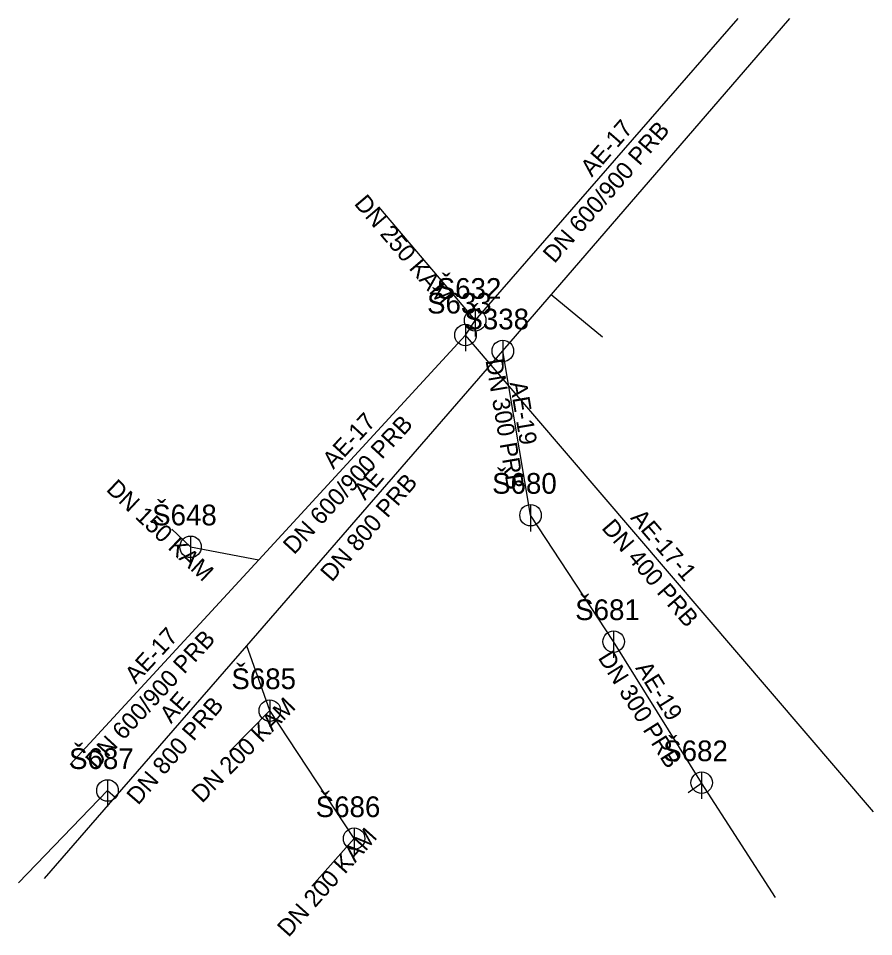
# Model space of a CAD drawing. Extents: x -483422.7 to -483343.1, y -1126332.9 to -1126247.5.
import ezdxf

# ---------------------------------------------------------------- set-up
doc = ezdxf.new("R2010")
doc.units = 0
for name, color, linetype in [('_pripojka_kanal_destova_priblizne_', 7, 'Continuous'), ('_pripojka_kanal_jednotna_priblizne_', 7, 'Continuous'), ('_stoka_jednotna_smvak_prevzato_z_dokumentace_', 7, 'Continuous'), ('Default', 7, 'Continuous'), ('MoLevel 119', 7, 'Continuous'), ('MoLevel 120', 7, 'Continuous'), ('MoLevel 124', 7, 'Continuous'), ('MoLevel 68', 7, 'Continuous'), ('MoLevel 69', 7, 'Continuous')]:
    doc.layers.add(name, color=color, linetype=linetype)

# ---------------------------------------------------------------- blocks, each defined once
blk = doc.blocks.new('_sachta_kanal_prevzato_z_dokumentace_')
at = {"layer": 'Default'}
blk.add_line((0, 0.00005), (0, -0.000075), dxfattribs=at)
blk.add_circle((0, 0), 0.00005, dxfattribs=at)

msp = doc.modelspace()

# ---------------------------------------------------------------- linework, layer by layer
at = {"layer": '_pripojka_kanal_destova_priblizne_'}
msp.add_line((-483368.347, -1126277.171), (-483373.113, -1126273.232), dxfattribs=at)
at = {"layer": '_pripojka_kanal_jednotna_priblizne_'}
for p, q in [((-483389.194, -1126265.038), (-483380.194, -1126275.606)), ((-483408.416, -1126295.029), (-483406.669, -1126296.67)), ((-483403.061, -1126315.703), (-483399.299, -1126311.9)), ((-483360.379, -1126319.511), (-483359.119, -1126318.6)), ((-483395.402, -1126328.222), (-483391.452, -1126323.799))]:
    msp.add_line(p, q, dxfattribs=at)
at = {"layer": '_stoka_jednotna_smvak_prevzato_z_dokumentace_'}
for p, q in [((-483380.195, -1126275.606), (-483355.729, -1126247.526)), ((-483377.62, -1126278.45), (-483350.913, -1126247.526)), ((-483381.094, -1126276.972), (-483380.195, -1126275.606)), ((-483400.333, -1126297.875), (-483381.094, -1126276.972)), ((-483343.12, -1126321.3), (-483381.094, -1126276.972)), ((-483401.431, -1126305.858), (-483377.62, -1126278.45)), ((-483375.04, -1126293.73), (-483377.62, -1126278.45)), ((-483367.31, -1126305.48), (-483375.04, -1126293.73)), ((-483406.67, -1126296.67), (-483400.333, -1126297.875)), ((-483417.865, -1126316.923), (-483400.333, -1126297.875)), ((-483413.676, -1126319.953), (-483401.431, -1126305.858)), ((-483399.3, -1126311.9), (-483401.431, -1126305.858)), ((-483359.12, -1126318.6), (-483367.31, -1126305.48)), ((-483391.453, -1126323.799), (-483399.3, -1126311.9)), ((-483352.241, -1126329.275), (-483359.12, -1126318.6)), ((-483422.692, -1126327.898), (-483414.396, -1126319.327)), ((-483414.396, -1126319.327), (-483413.676, -1126319.953)), ((-483420.25, -1126327.52), (-483413.676, -1126319.953))]:
    msp.add_line(p, q, dxfattribs=at)

# ---------------------------------------------------------------- block references
at = {"layer": 'MoLevel 119', "xscale": 20000, "yscale": 20000}
for p in [(-483380.195, -1126275.606), (-483381.094, -1126276.972), (-483377.62, -1126278.45), (-483375.04, -1126293.73), (-483406.67, -1126296.67), (-483367.31, -1126305.48), (-483399.3, -1126311.9), (-483359.12, -1126318.6), (-483414.396, -1126319.327), (-483391.453, -1126323.799)]:
    msp.add_blockref('_sachta_kanal_prevzato_z_dokumentace_', p, dxfattribs=at)

# ---------------------------------------------------------------- texts
at = {"layer": 'MoLevel 120'}
for s, p in [('Š632', (-483383.772, -1126273.606)), ('Š633', (-483384.671, -1126274.972)), ('Š338', (-483381.197, -1126276.45)), ('Š680', (-483378.617, -1126291.73)), ('Š648', (-483410.247, -1126294.67)), ('Š681', (-483370.887, -1126303.48)), ('Š685', (-483402.877, -1126309.9)), ('Š682', (-483362.697, -1126316.6)), ('Š687', (-483417.973, -1126317.327)), ('Š686', (-483395.03, -1126321.799))]:
    msp.add_text(s, height=1.9259, dxfattribs=at).set_placement(p)
at = {"layer": 'MoLevel 124'}
for s, rotation, p in [('DN 250 KAM', 310.4173, (-483391.521, -1126264.781)), ('DN 150 KAM', 316.78983, (-483414.603, -1126291.42)), ('DN 200 KAM', 45.31702, (-483405.602, -1126320.556)), ('DN 200 KAM', 48.23884, (-483397.557, -1126333.046))]:
    msp.add_text(s, height=1.6049, rotation=rotation, dxfattribs=at).set_placement(p)
at = {"layer": 'MoLevel 68'}
for s, height, rotation, p in [('DN 600/900 PRB', 1.60494, 48.93483, (-483372.821, -1126270.386)), ('DN 300 PRB', 1.6049, 279.58389, (-483379.236, -1126279.32)), ('DN 600/900 PRB', 1.60494, 47.37371, (-483397.037, -1126297.464)), ('DN 800 PRB', 1.6049, 49.01716, (-483393.527, -1126300.007)), ('DN 400 PRB', 1.6049, 310.58533, (-483368.497, -1126294.944)), ('DN 600/900 PRB', 1.60494, 47.37317, (-483415.423, -1126317.44)), ('DN 300 PRB', 1.6049, 301.97397, (-483368.813, -1126306.987)), ('DN 800 PRB', 1.6049, 49.01759, (-483411.555, -1126320.758))]:
    msp.add_text(s, height=height, rotation=rotation, dxfattribs=at).set_placement(p)
at = {"layer": 'MoLevel 69'}
for s, rotation, p in [('AE-17', 48.93483, (-483369.337, -1126262.344)), ('AE-19', 279.58389, (-483376.985, -1126281.409)), ('AE-17', 47.37371, (-483393.379, -1126289.519)), ('AE', 49.01716, (-483390.453, -1126292.421)), ('AE-17-1', 310.58533, (-483365.811, -1126294.012)), ('AE-17', 47.37317, (-483411.764, -1126309.495)), ('AE-19', 301.97397, (-483365.327, -1126307.941)), ('AE', 49.01759, (-483408.481, -1126313.173))]:
    msp.add_text(s, height=1.6049, rotation=rotation, dxfattribs=at).set_placement(p)

doc.saveas('drawing.dxf')
